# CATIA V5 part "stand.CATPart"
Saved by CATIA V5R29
Part number: stand
Revision: HERHANG?
Definition: B??MEYEN
Nomenclature: stand
Source: Unknown
Bounding box of the stored display mesh (mm): x -658.284 to 658.284, y -1814.076 to -187.275, z -1108.284 to 48.284
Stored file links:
  C:\가치같이\SmartFactory_Freeze dryer\stand.CATPart
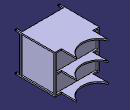
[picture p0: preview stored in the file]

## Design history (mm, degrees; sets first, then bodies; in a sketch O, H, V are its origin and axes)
Body1 "Y?seklik-Ekstr?yon9" (main body)
  Solid1: solid without history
